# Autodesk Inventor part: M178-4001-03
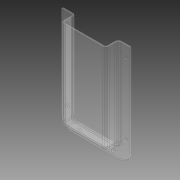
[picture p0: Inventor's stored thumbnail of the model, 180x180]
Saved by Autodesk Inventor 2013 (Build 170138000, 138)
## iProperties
Created: 2004-11
Part Number: M178-4001-03
Material: Plastic, Clear
Document SubType Name: Modeling
Designer: Autodesk, Inc.
Manufacturer: Standard
Standards Organization: Custom
Description: TOOL CADDY, PLASTIC, 2 x 4 x 0.625
Mass: 26.1813 g
Surface Area: 237.698 cm^2
Volume: 21.8178 cm^3
Density: 1.2 g/cm^3
CAGE: 1LJX3
Dept. ID: Product Design
Description #2: ---
Finish #1: ---
Finish #2: ---
Material ID: ---
Project Number: ---
Author: Autodesk, Inc.
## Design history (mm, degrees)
derived "M178-4001-XX.ipt"
body "Solid1"
tag "TaggingFeature2"
feature "Solid1::M178-4001-XX.ipt" dims "ScaleForDerivedMember" = 10
